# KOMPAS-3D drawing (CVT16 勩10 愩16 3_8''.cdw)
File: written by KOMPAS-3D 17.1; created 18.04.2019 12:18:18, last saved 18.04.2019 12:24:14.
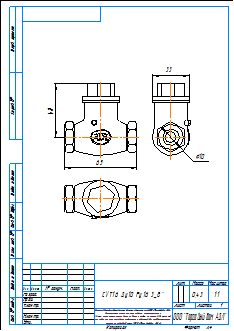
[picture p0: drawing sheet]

Sheet 1: A4, portrait

Title block, sheet 1: name: CVT16 Ду10 Ру16 3_8''; material: Внимание! Данный продукт является объектом авторского права ООО «Торговый Дом АДЛ». / Запрещается изменение, копирование, распространение / (в том числе путем копирования на другие сайты и ресурсы в Интернете) / или любое иное использование информации и объектов без предварительного / согласия правообладателя (ООО «Торговый Дом АДЛ»).; mass: 0,43; sheets: 1; organisation: ООО "Торговый дом АДЛ"; sheet format: A4; stored path: \\adlc.lan\data\АДЛ_ПКД\3D-модели\ADL production\Клапаны обратные ГРАНЛОК\CVT16 Затвор обратный поворотный резьбовой\KOMPAS 2D\CVT16 Ду10 Ру16 3_8''.cdw

Views: Вид 1, Проекционный вид 2, Проекционный вид 3
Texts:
  user
Dimensions and other numbers on the sheet: 65; 48; 10; 33; 1:1; 1; 0,43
